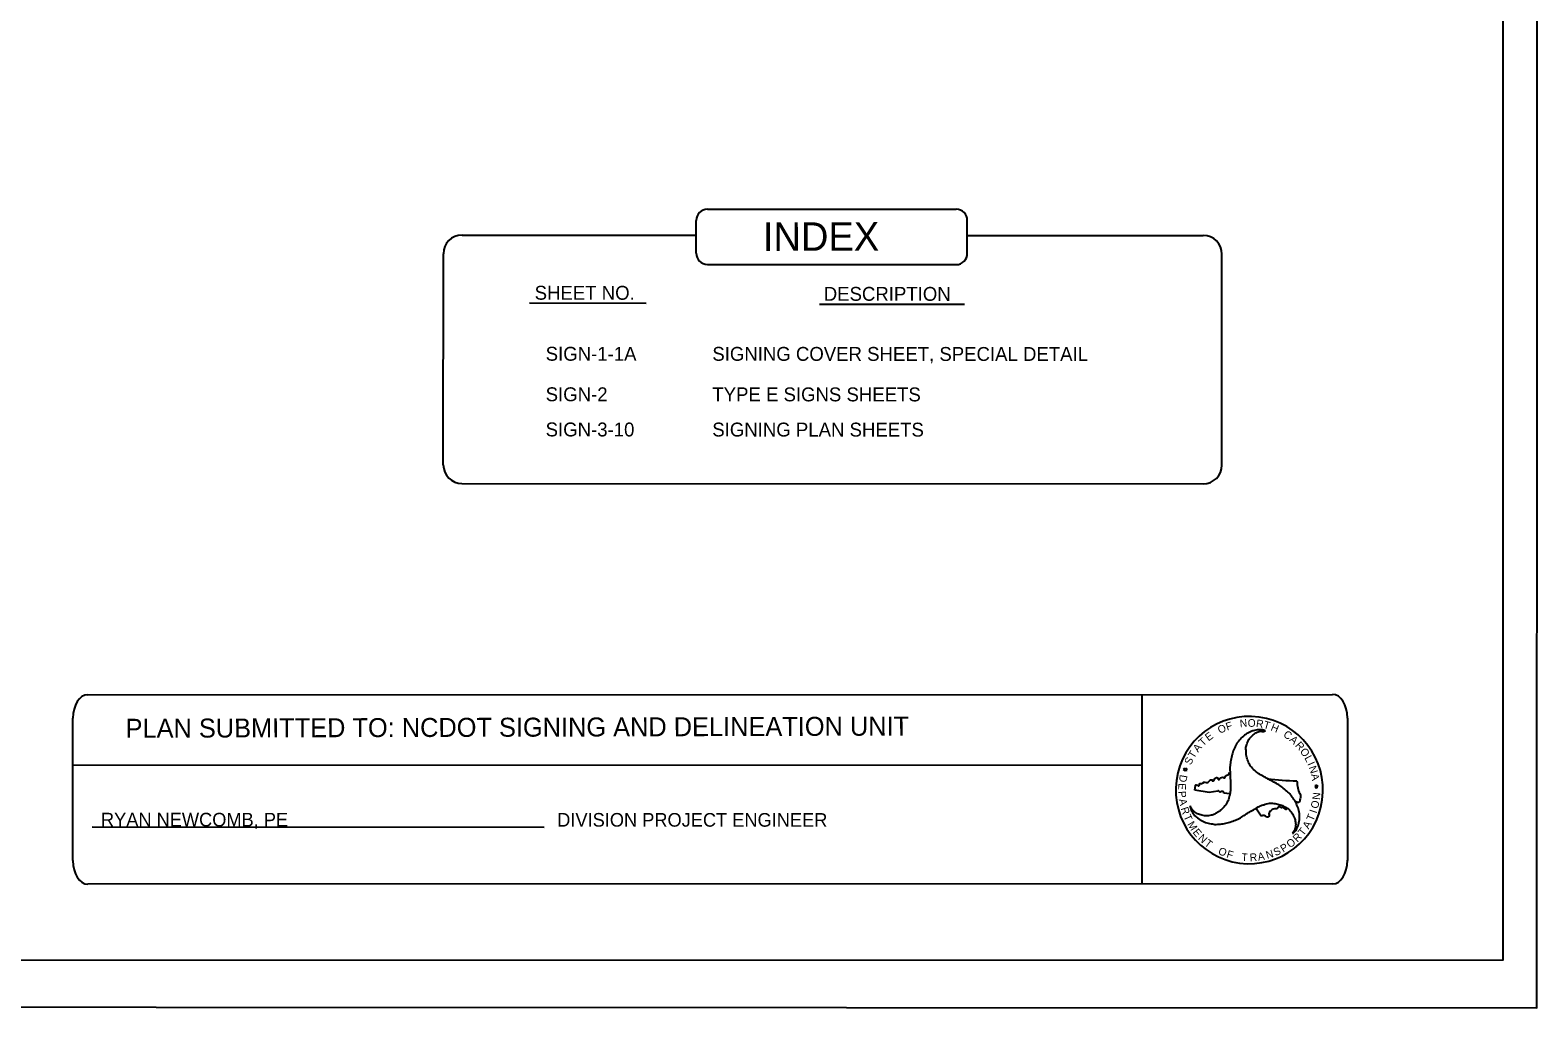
# Model space of a CAD drawing. Extents: x 50703 to 52785, y 49383 to 50479.
# Drawn here: x 51651 to 52386, y 49383 to 49859 of the extents above; entities that cross this region are included whole.
import ezdxf

# ---------------------------------------------------------------- set-up
doc = ezdxf.new("R2010")
doc.units = 0
for name, color, linetype in [('Default', 7, 'Continuous'), ('Old_Level_18', 7, 'Continuous'), ('Sheet Plot Border Outside CELL', 7, 'Continuous'), ('Sheet Title CELL', 7, 'Continuous')]:
    doc.layers.add(name, color=color, linetype=linetype)

msp = doc.modelspace()

# ---------------------------------------------------------------- linework, layer by layer
at = {"layer": 'Default'}
for p, q in [((51679.08, 49535.15), (52286, 49535.32)), ((52192.94, 49535.3), (52192.98, 49442.95)), ((51671.91, 49454.34), (51671.88, 49523.71)), ((52293.21, 49523.84), (52293.23, 49454.47)), ((51671.87, 49500.79), (52192.95, 49501.08)), ((51681.34, 49470.81), (51901.65, 49470.7)), ((52286.03, 49442.98), (51679.11, 49442.79))]:
    msp.add_line(p, q, dxfattribs=at)
for centre, major_axis, start_param, end_param in [((51679.08, 49523.71), (0, 11.49), 0.000702, 1.571498), ((52286.01, 49523.83), (0, 11.49), 4.713091, 6.283887), ((51679.11, 49454.34), (0, -11.49), 4.713091, 6.283887), ((52286.03, 49454.47), (0, -11.49), 0.000702, 1.571498)]:
    msp.add_ellipse(centre, major_axis=major_axis, ratio=0.62659, start_param=start_param, end_param=end_param, dxfattribs=at)
at = {"layer": 'Old_Level_18'}
msp.add_lwpolyline([(52369.04, 50455.98), (50869.05, 50455.87), (50869.12, 49405.87), (52369.12, 49405.98)], close=True, dxfattribs=at)
at = {"layer": 'Sheet Plot Border Outside CELL'}
msp.add_lwpolyline([(52386.04, 50478.48), (50703.13, 50479.27), (50702.62, 49383.36), (52385.53, 49382.58)], close=True, dxfattribs=at)
at = {"layer": 'Sheet Title CELL'}
for p, q in [((51975.74, 49750.35), (51975.75, 49766.37)), ((52107.9, 49750.29), (52107.91, 49766.31)), ((51861.6, 49759.2), (51975.74, 49759.14)), ((52107.9, 49759.08), (52222.96, 49759.03)), ((51852.46, 49647.24), (51852.51, 49750.11)), ((52232, 49647.06), (52232.05, 49749.94)), ((51894.51, 49726.14), (51951.37, 49726.11)), ((52035.9, 49725.62), (52106.54, 49725.59)), ((51861.55, 49638.14), (52222.91, 49637.98)), ((52253.24, 49517.59), (52253.17, 49517.52)), ((52253.24, 49517.59), (52253.17, 49517.52)), ((52213.81, 49498.69), (52213.34, 49499.15)), ((52213.34, 49499.15), (52213.99, 49499.06)), ((52213.54, 49498.1), (52213.81, 49498.69)), ((52214.09, 49498.42), (52213.54, 49498.1)), ((52213.99, 49499.06), (52214.25, 49499.63)), ((52214.56, 49497.96), (52214.09, 49498.42)), ((52214.25, 49499.63), (52214.39, 49499.01)), ((52214.39, 49499.01), (52215.03, 49498.92)), ((52215.03, 49498.92), (52214.45, 49498.61)), ((52214.45, 49498.61), (52214.56, 49497.96)), ((52218.78, 49488.69), (52219.16, 49490.92)), ((52225.79, 49487.49), (52218.78, 49488.69)), ((52229.98, 49488.14), (52225.79, 49487.49)), ((52254.18, 49494.26), (52254.18, 49494.26)), ((52277.96, 49490.77), (52277.32, 49490.85)), ((52277.32, 49490.85), (52277.8, 49490.41)), ((52277.8, 49490.41), (52277.53, 49489.82)), ((52277.53, 49489.82), (52278.07, 49490.13)), ((52278.23, 49491.34), (52277.96, 49490.77)), ((52278.07, 49490.13), (52278.54, 49489.68)), ((52278.38, 49490.71), (52278.23, 49491.34)), ((52279.01, 49490.65), (52278.38, 49490.71)), ((52278.44, 49490.32), (52279.01, 49490.65)), ((52278.54, 49489.68), (52278.44, 49490.32)), ((52235.96, 49486.85), (52233.02, 49487.27)), ((52251.23, 49476.05), (52248.56, 49479.84)), ((52248.56, 49479.84), (52248.56, 49479.84))]:
    msp.add_line(p, q, dxfattribs=at)
for points in [[(51981.2, 49771.82), (52102.46, 49771.77)], [(51981.19, 49744.89), (52102.44, 49744.84)]]:
    msp.add_lwpolyline(points, dxfattribs=at)
for centre, radius, start, end in [((51981.2, 49766.37), 5.45, 89.97341, 179.97341), ((52102.45, 49766.32), 5.45, 359.97341, 89.97341), ((51861.6, 49750.11), 9.09, 89.97341, 179.97341), ((52222.96, 49749.94), 9.09, 359.97341, 89.97341), ((51981.19, 49750.35), 5.45, 179.97341, 269.97341), ((52102.45, 49750.29), 5.45, 269.97341, 359.97341), ((51861.55, 49647.23), 9.09, 179.97341, 269.97341), ((52222.91, 49647.06), 9.09, 269.97341, 359.97341), ((52245.4, 49488.71), 35.88, 352.42777, 172.42777), ((52276.37, 49690.43), 197.41, 258.10627, 258.20586), ((52245.4, 49488.71), 35.88, 172.42777, 352.42777), ((52276.37, 49690.43), 197.41, 263.54532, 267.75133)]:
    msp.add_arc(centre, radius, start, end, dxfattribs=at)
for points in [[(52253.17, 49517.52), (52252.36, 49517.85), (52249.88, 49518.08), (52247.27, 49517.61), (52247.03, 49517.52), (52245.69, 49517.02), (52244.23, 49516.21), (52241.96, 49514.57), (52240.11, 49512.44), (52239.36, 49511.52), (52238.74, 49510.35), (52237.57, 49507.84), (52236.81, 49505.36), (52236.25, 49502.43), (52235.95, 49499.82), (52236.02, 49497.12), (52236.13, 49494.38), (52236.17, 49491.73), (52236.18, 49489.01), (52235.84, 49486.36), (52235.79, 49486.13), (52234.95, 49483.37), (52233.47, 49481.04), (52231.72, 49479.16), (52230.73, 49478.32), (52229.35, 49477.51), (52228.57, 49477.05), (52226.78, 49476.41), (52224.16, 49476.16), (52221.69, 49476.63), (52219.56, 49477.48), (52217.79, 49478.98), (52216.5, 49480.97)], [(52266.51, 49467.5), (52267.16, 49468.02), (52268.62, 49470.06), (52269.52, 49472.55), (52269.59, 49472.8), (52269.8, 49474.22), (52269.84, 49475.91), (52269.58, 49478.68), (52268.62, 49481.34), (52268.22, 49482.46), (52267.5, 49483.59), (52265.92, 49485.85), (52264.17, 49487.75), (52261.89, 49489.69), (52259.78, 49491.24), (52257.39, 49492.56), (52254.99, 49493.82), (52252.69, 49495.1), (52250.29, 49496.47), (52248.19, 49498.08), (52248.02, 49498.25), (52246.02, 49500.38), (52244.75, 49502.82), (52243.98, 49505.26), (52243.79, 49506.53), (52243.78, 49508.13), (52243.73, 49509.05), (52244.11, 49510.91), (52245.2, 49513.33), (52246.82, 49515.2), (52248.63, 49516.61), (52250.83, 49517.39), (52253.17, 49517.52), (52253.24, 49517.59)], [(52219.16, 49490.92), (52219.11, 49491.14), (52219.51, 49491.33), (52220.5, 49490.76), (52221.09, 49491.14), (52221.13, 49491.59), (52221.6, 49491.99), (52222.3, 49491.75), (52223.06, 49492.49), (52223.67, 49492.55), (52224.93, 49492.39), (52226.61, 49493.69), (52227.25, 49493.69), (52227.35, 49493.28), (52227.73, 49493.15), (52228.53, 49494.29), (52228.72, 49494.45), (52229.94, 49494.76), (52230.22, 49494.49), (52230.24, 49493.93), (52230.39, 49493.8), (52230.81, 49494.02), (52231.41, 49494.62), (52232.44, 49494.98), (52233.51, 49494.71), (52233.81, 49495.57), (52235.2, 49496.26), (52235.54, 49496.74), (52235.67, 49497.26)], [(52236.02, 49497.18), (52236.02, 49497.12), (52236.13, 49494.38), (52236.17, 49491.73), (52236.18, 49489.01), (52235.95, 49486.85)], [(52233.02, 49487.27), (52232.81, 49487.85), (52232.26, 49488.09), (52231.43, 49487.78), (52230.86, 49487.89), (52230.28, 49488.44), (52229.98, 49488.14)], [(52268, 49482.89), (52267.5, 49483.59), (52265.92, 49485.85), (52264.17, 49487.75), (52261.89, 49489.69), (52259.78, 49491.24), (52257.39, 49492.56), (52254.99, 49493.82), (52254.18, 49494.26)], [(52268.62, 49493.16), (52268.82, 49490.62), (52269.73, 49487.53), (52270.36, 49485.82), (52270.15, 49484.45), (52269.62, 49482.85), (52268.01, 49482.9)], [(52216.5, 49480.97), (52216.65, 49480.1), (52217.69, 49477.83), (52219.38, 49475.79), (52219.58, 49475.66), (52220.7, 49474.71), (52222.13, 49473.87), (52224.68, 49472.71), (52227.44, 49472.2), (52228.61, 49471.99), (52229.99, 49472.06), (52232.69, 49472.3), (52235.2, 49472.85), (52238.05, 49473.85), (52240.42, 49474.89), (52242.76, 49476.31), (52245.06, 49477.79), (52247.35, 49479.13), (52249.71, 49480.48), (52252.17, 49481.53), (52252.43, 49481.6), (52255.25, 49482.26), (52257.97, 49482.14), (52260.45, 49481.59), (52261.72, 49481.14), (52263.06, 49480.32), (52263.91, 49479.91), (52265.32, 49478.66), (52266.84, 49476.52), (52267.67, 49474.17), (52267.99, 49471.87), (52267.57, 49469.59), (52266.51, 49467.5)], [(52248.56, 49479.84), (52249.71, 49480.48), (52252.17, 49481.53), (52252.43, 49481.6), (52255.25, 49482.26), (52257.97, 49482.14), (52260.45, 49481.59), (52261.72, 49481.14), (52263.06, 49480.32), (52263.84, 49479.93)], [(52263.83, 49479.92), (52263.4, 49479.31), (52262.84, 49479.34), (52261.96, 49480.26), (52260.73, 49480.17), (52260.22, 49480.56), (52259.86, 49480.62), (52258.85, 49479.65), (52257.62, 49479.54), (52255.51, 49478.38), (52255, 49477.61), (52254.91, 49475.81), (52254.39, 49475.52), (52253.83, 49475.68), (52252.7, 49476.3), (52251.23, 49476.05)]]:
    msp.add_spline(points, degree=3, dxfattribs=at)

# ---------------------------------------------------------------- texts
at = {"layer": 'Default'}
for s, height, rotation, p in [('INDEX', 13.866, 0.15565, (52008.29, 49751.5)), ('SHEET NO.', 6.771, 359.97341, (51896.99, 49727.71)), ('DESCRIPTION', 6.7709, 359.97341, (52037.93, 49727.19)), ('SIGN-1-1A', 6.771, 359.97341, (51902.36, 49697.98)), ('SIGNING COVER SHEET, SPECIAL DETAIL', 6.7709, 359.97341, (51983.61, 49697.94)), ('SIGN-2', 6.771, 359.97341, (51902.35, 49678.24)), ('TYPE E SIGNS SHEETS', 6.7709, 359.97341, (51983.6, 49678.2)), ('SIGN-3-10', 6.771, 359.97341, (51902.34, 49661.09)), ('SIGNING PLAN SHEETS', 6.7709, 359.97341, (51983.59, 49661.05)), ('PLAN SUBMITTED TO: NCDOT SIGNING AND DELINEATION UNIT', 9.2466, 0.1623, (51697.57, 49514.19)), ('RYAN NEWCOMB, PE', 6.6381, 359.97341, (51685.56, 49471.01)), ('DIVISION PROJECT ENGINEER', 6.6381, 359.97341, (51907.99, 49470.91))]:
    msp.add_text(s, height=height, rotation=rotation, dxfattribs=at).set_placement(p)
at = {"layer": 'Sheet Title CELL'}
for s, height, rotation, p in [('E', 3.72, 36.58471, (52225.49, 49512.39)), ('O', 3.74, 24.64533, (52231, 49516.07)), ('F', 3.74, 17.49849, (52234.59, 49517.69)), ('N', 3.73, 5.41155, (52240.89, 49519.31)), ('O', 3.74, 357.91344, (52244.52, 49519.63)), ('R', 3.73, 351.30351, (52248.47, 49519.49)), ('T', 3.74, 344.65388, (52252, 49518.95)), ('H', 3.73, 337.56916, (52255.52, 49517.96)), ('C', 3.72, 325.22681, (52261.63, 49515.06)), ('A', 3.75, 50.75556, (52220.39, 49506.88)), ('T', 3.72, 43.70034, (52222.84, 49509.87)), ('A', 3.73, 317.72978, (52264.68, 49512.92)), ('R', 3.73, 311.36583, (52267.52, 49510.35)), ('S', 3.73, 64.18402, (52216.85, 49500.63)), ('T', 3.74, 57.80787, (52218.41, 49503.82)), ('O', 3.74, 304.24623, (52269.87, 49507.66)), ('L', 3.72, 298.01255, (52272.11, 49504.38)), ('I', 3.74, 294.02321, (52273.56, 49501.5)), ('D', 3.73, 260.28077, (52211.59, 49496.4)), ('N', 3.73, 288.32311, (52274.28, 49499.82)), ('A', 3.73, 280.89113, (52275.41, 49496.34)), ('E', 3.72, 266.56866, (52210.9, 49492.17)), ('P', 3.73, 274.10105, (52210.73, 49488.12)), ('A', 3.73, 280.69363, (52211.02, 49484.14)), ('R', 3.73, 287.76227, (52211.89, 49479.8)), ('O', 3.72, 77.38789, (52278.83, 49479.42)), ('N', 3.73, 84.6359, (52279.78, 49483.83)), ('T', 3.73, 294.4128, (52213.18, 49475.89)), ('M', 3.72, 301.64784, (52214.99, 49472.06)), ('A', 3.74, 59.51793, (52274.27, 49469.42)), ('T', 3.73, 66.60235, (52276.47, 49473.25)), ('I', 3.74, 72.25226, (52278.13, 49477.13)), ('E', 3.72, 309.11461, (52217.55, 49468.06)), ('N', 3.74, 316.08615, (52220.13, 49464.96)), ('R', 3.74, 45.3311, (52268.81, 49463.09)), ('T', 3.72, 51.43089, (52271.68, 49466.07)), ('T', 3.73, 322.92815, (52223.19, 49462.07)), ('O', 3.73, 336.23184, (52229.85, 49457.7)), ('F', 3.73, 343.39707, (52234.01, 49455.94)), ('A', 3.72, 10.01605, (52249.79, 49454.3)), ('N', 3.72, 17.04768, (52254.12, 49455.13)), ('S', 3.72, 24.25815, (52258.14, 49456.45)), ('P', 3.73, 31.45, (52261.89, 49458.16)), ('O', 3.74, 38.14199, (52265.28, 49460.28)), ('T', 3.72, 356.3063, (52241.45, 49454.23)), ('R', 3.74, 3.26292, (52245.67, 49454.01))]:
    msp.add_text(s, height=height, rotation=rotation, dxfattribs=at).set_placement(p)

doc.saveas('drawing.dxf')
